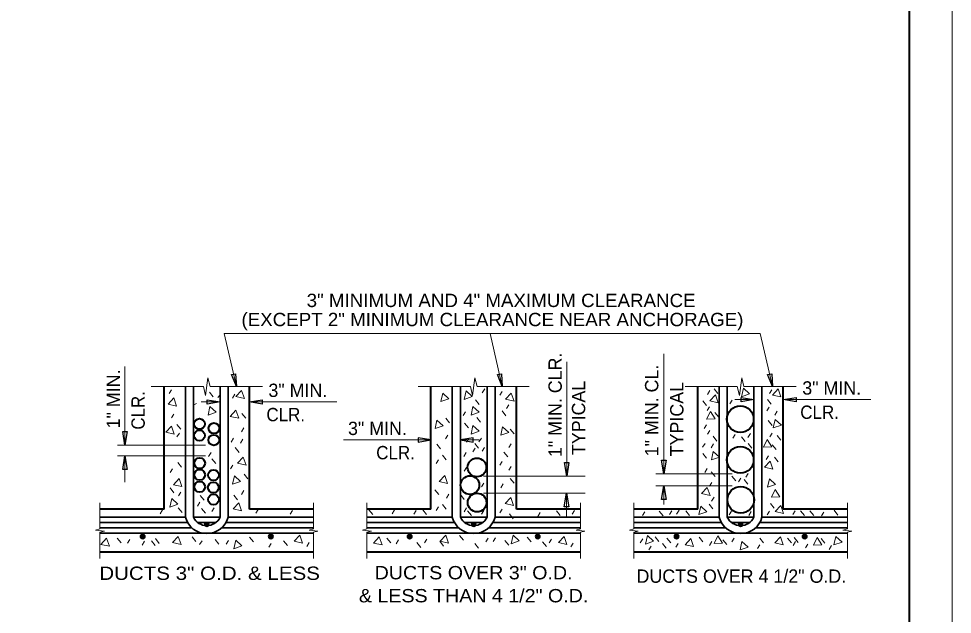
# Model space of a CAD drawing. Extents: x 0 to 22.7, y 0 to 15.6.
# Drawn here: x 15.38 to 22.67, y 4.57 to 9.22 of the extents above; entities that cross this region are included whole.
import ezdxf
from ezdxf.enums import TextEntityAlignment as Align

# ---------------------------------------------------------------- set-up
doc = ezdxf.new("R2010")
doc.units = 0
doc.header["$LTSCALE"] = 0.042
doc.linetypes.add('SHORT_DASHED', pattern=[2.7, 1.5, -1.2])
for name, color, linetype, lineweight in [('1', 7, 'Continuous', 13), ('2', 7, 'SHORT_DASHED', 25), ('3', 7, 'Continuous', 35), ('4', 7, 'Continuous', 13), ('7', 7, 'Continuous', 13)]:
    doc.layers.add(name, color=color, linetype=linetype, lineweight=lineweight)

msp = doc.modelspace()

# ---------------------------------------------------------------- linework, layer by layer
at = {"layer": '1'}
for p, q in [((21.16781, 6.76354), (16.98427, 6.76354)), ((16.82161, 6.34802), (16.41365, 6.34802)), ((17.28167, 6.34802), (16.8737, 6.34802)), ((18.90495, 6.34802), (18.49698, 6.34802)), ((19.365, 6.34802), (18.95703, 6.34802)), ((20.98828, 6.34802), (20.58031, 6.34802)), ((21.44839, 6.34802), (21.04036, 6.34802)), ((21.34964, 6.24552), (21.34766, 6.24552)), ((16.01432, 5.23604), (16.01432, 5.44005)), ((17.68099, 5.23604), (17.68099, 5.44005)), ((18.09766, 5.23604), (18.09766, 5.44005)), ((19.76432, 5.23604), (19.76432, 5.44005)), ((20.18099, 5.23604), (20.18099, 5.44005)), ((21.84766, 5.23604), (21.84766, 5.44005)), ((16.01432, 5.00604), (16.01432, 5.21)), ((17.68099, 5.00604), (17.68099, 5.21)), ((18.09766, 5.00604), (18.09766, 5.21)), ((19.76432, 5.00604), (19.76432, 5.21)), ((20.18099, 5.00604), (20.18099, 5.21)), ((21.84766, 5.00604), (21.84766, 5.21))]:
    msp.add_line(p, q, dxfattribs=at)
at = {"layer": '1', "lineweight": 40}
for p, q in [((16.51432, 5.38969), (16.51432, 6.34802)), ((17.18099, 5.38969), (17.18099, 6.34802)), ((18.59766, 5.38969), (18.59766, 6.34802)), ((19.26432, 5.38969), (19.26432, 6.34802)), ((20.68099, 5.38969), (20.68099, 6.34802)), ((21.34766, 5.38969), (21.34766, 6.34802)), ((16.51432, 5.38969), (16.01432, 5.38969)), ((17.68099, 5.38969), (17.18099, 5.38969)), ((18.59766, 5.38969), (18.09766, 5.38969)), ((19.76432, 5.38969), (19.26432, 5.38969)), ((20.68099, 5.38969), (20.18099, 5.38969)), ((21.84766, 5.38969), (21.34766, 5.38969)), ((16.01432, 5.05635), (17.68099, 5.05635)), ((18.09766, 5.05635), (19.76432, 5.05635)), ((20.18099, 5.05635), (21.84766, 5.05635))]:
    msp.add_line(p, q, dxfattribs=at)
at = {"layer": '1'}
msp.add_lwpolyline([(0, 0), (22.66667, 0), (22.66667, 14.66667), (0, 14.66667)], close=True, dxfattribs=at)
at = {"layer": '1', "lineweight": 40}
msp.add_lwpolyline([(22.33333, 0.33333), (22.33333, 14.33333), (1, 14.33333), (1, 0.33333)], close=True, dxfattribs=at)
at = {"layer": '1'}
for points in [[(16.82161, 6.34802), (16.83896, 6.27859), (16.85635, 6.4175), (16.8737, 6.34802)], [(18.90495, 6.34802), (18.92229, 6.27859), (18.93969, 6.4175), (18.95703, 6.34802)], [(20.98828, 6.34802), (21.00568, 6.27859), (21.02302, 6.4175), (21.04036, 6.34802)], [(16.01432, 5.23604), (15.97958, 5.2274), (16.04906, 5.2187), (16.01432, 5.21)], [(17.68099, 5.23604), (17.64625, 5.2274), (17.71573, 5.2187), (17.68099, 5.21)], [(18.09766, 5.23604), (18.06292, 5.2274), (18.1324, 5.2187), (18.09766, 5.21)], [(19.76432, 5.23604), (19.72958, 5.2274), (19.79906, 5.2187), (19.76432, 5.21)], [(20.18099, 5.23604), (20.1463, 5.2274), (20.21573, 5.2187), (20.18099, 5.21)], [(21.84766, 5.23604), (21.81297, 5.2274), (21.8824, 5.2187), (21.84766, 5.21)]]:
    msp.add_lwpolyline(points, dxfattribs=at)
at = {"layer": '1', "lineweight": 40}
for centre, radius in [((21.01194, 6.09394), 0.10417), ((16.79099, 6.05634), 0.04167), ((16.90411, 6.0228), 0.04167), ((16.79099, 5.96623), 0.04167), ((16.90234, 5.93087), 0.04167), ((21.01194, 5.77545), 0.10417), ((16.79276, 5.75066), 0.04167), ((18.95649, 5.71696), 0.07292), ((16.79276, 5.65878), 0.04167), ((16.90057, 5.65701), 0.04167), ((18.90201, 5.57905), 0.07292), ((16.79276, 5.56514), 0.04167), ((16.8988, 5.55983), 0.04167), ((21.01543, 5.46389), 0.10417), ((16.90057, 5.46618), 0.04167), ((18.95774, 5.44243), 0.07292)]:
    msp.add_circle(centre, radius, dxfattribs=at)
at = {"layer": '2', "linetype": 'Continuous', "lineweight": 35}
for centre, radius in [((16.8474, 5.27233), 0.00173), ((16.8475, 5.27248), 0.000295), ((18.93071, 5.27233), 0.00173), ((18.93082, 5.27248), 0.000295), ((21.01408, 5.27233), 0.00173), ((21.01418, 5.27248), 0.000295)]:
    msp.add_circle(centre, radius, dxfattribs=at)
at = {"layer": '3'}
for p, q in [((16.68099, 5.32719), (16.68099, 6.34802)), ((16.74349, 5.32719), (16.74349, 6.34802)), ((16.95182, 5.32719), (16.95182, 6.34802)), ((17.01432, 5.32719), (17.01432, 6.34802)), ((18.76432, 5.32719), (18.76432, 6.34802)), ((18.82682, 5.32719), (18.82682, 6.34802)), ((19.03516, 5.32719), (19.03516, 6.34802)), ((19.09766, 5.32719), (19.09766, 6.34802)), ((20.84766, 5.32719), (20.84766, 6.34802)), ((20.91016, 5.32719), (20.91016, 6.34802)), ((21.11849, 5.32719), (21.11849, 6.34802)), ((21.18099, 5.32719), (21.18099, 6.34802)), ((16.01432, 5.32719), (16.68099, 5.32719)), ((16.74349, 5.32719), (16.95182, 5.32719)), ((17.01432, 5.32719), (17.68099, 5.32719)), ((18.09766, 5.32719), (18.76432, 5.32719)), ((18.82682, 5.32719), (19.03516, 5.32719)), ((19.09766, 5.32719), (19.76432, 5.32719)), ((20.18099, 5.32719), (20.84766, 5.32719)), ((20.91016, 5.32719), (21.11849, 5.32719)), ((21.18099, 5.32719), (21.84766, 5.32719)), ((16.01432, 5.28552), (16.69885, 5.28552)), ((16.77833, 5.28552), (16.9175, 5.28552)), ((16.99729, 5.28552), (17.68099, 5.28552)), ((18.09766, 5.28552), (18.78219, 5.28552)), ((18.86167, 5.28552), (19.00083, 5.28552)), ((19.08063, 5.28552), (19.76432, 5.28552)), ((20.18099, 5.28552), (20.86557, 5.28552)), ((20.94505, 5.28552), (21.08422, 5.28552)), ((21.16401, 5.28552), (21.84766, 5.28552)), ((16.01432, 5.24385), (16.7324, 5.24385)), ((16.01432, 5.20219), (17.68099, 5.20219)), ((16.96297, 5.24385), (17.68099, 5.24385)), ((18.09766, 5.24385), (18.81573, 5.24385)), ((18.09766, 5.20219), (19.76432, 5.20219)), ((19.0463, 5.24385), (19.76432, 5.24385)), ((20.18099, 5.24385), (20.89911, 5.24385)), ((20.18099, 5.20219), (21.84766, 5.20219)), ((21.12964, 5.24385), (21.84766, 5.24385))]:
    msp.add_line(p, q, dxfattribs=at)
for centre, radius in [((16.84764, 5.27225), 0.01565), ((16.84739, 5.27234), 0.01486), ((16.84739, 5.27234), 0.01486), ((16.84739, 5.27234), 0.01486), ((16.84715, 5.27243), 0.01412), ((16.84715, 5.27243), 0.01412), ((16.84715, 5.27243), 0.01412), ((16.84692, 5.27251), 0.01341), ((16.84764, 5.27225), 0.01043), ((16.84739, 5.27234), 0.00991), ((16.84739, 5.27234), 0.00991), ((16.84739, 5.27234), 0.00991), ((16.84715, 5.27243), 0.00941), ((16.84715, 5.27243), 0.00941), ((16.84715, 5.27243), 0.00941), ((16.84692, 5.27251), 0.00894), ((16.84764, 5.27225), 0.00522), ((16.84739, 5.27234), 0.00496), ((16.84739, 5.27234), 0.00496), ((16.84739, 5.27234), 0.00496), ((16.84715, 5.27243), 0.00471), ((16.84715, 5.27243), 0.00471), ((16.84715, 5.27243), 0.00471), ((16.84692, 5.27251), 0.00447), ((18.93096, 5.27225), 0.01565), ((18.93071, 5.27234), 0.01486), ((18.93071, 5.27234), 0.01486), ((18.93071, 5.27234), 0.01486), ((18.93047, 5.27243), 0.01412), ((18.93047, 5.27243), 0.01412), ((18.93047, 5.27243), 0.01412), ((18.93024, 5.27251), 0.01341), ((18.93096, 5.27225), 0.01043), ((18.93071, 5.27234), 0.00991), ((18.93071, 5.27234), 0.00991), ((18.93071, 5.27234), 0.00991), ((18.93047, 5.27243), 0.00941), ((18.93047, 5.27243), 0.00941), ((18.93047, 5.27243), 0.00941), ((18.93024, 5.27251), 0.00894), ((18.93096, 5.27225), 0.00522), ((18.93071, 5.27234), 0.00496), ((18.93071, 5.27234), 0.00496), ((18.93071, 5.27234), 0.00496), ((18.93047, 5.27243), 0.00471), ((18.93047, 5.27243), 0.00471), ((18.93047, 5.27243), 0.00471), ((18.93024, 5.27251), 0.00447), ((21.01433, 5.27225), 0.01565), ((21.01408, 5.27234), 0.01486), ((21.01408, 5.27234), 0.01486), ((21.01408, 5.27234), 0.01486), ((21.01384, 5.27243), 0.01412), ((21.01384, 5.27243), 0.01412), ((21.01384, 5.27243), 0.01412), ((21.01361, 5.27251), 0.01341), ((21.01433, 5.27225), 0.01043), ((21.01408, 5.27234), 0.00991), ((21.01408, 5.27234), 0.00991), ((21.01408, 5.27234), 0.00991), ((21.01384, 5.27243), 0.00941), ((21.01384, 5.27243), 0.00941), ((21.01384, 5.27243), 0.00941), ((21.01361, 5.27251), 0.00894), ((21.01433, 5.27225), 0.00522), ((21.01408, 5.27234), 0.00496), ((21.01408, 5.27234), 0.00496), ((21.01408, 5.27234), 0.00496), ((21.01384, 5.27243), 0.00471), ((21.01384, 5.27243), 0.00471), ((21.01384, 5.27243), 0.00471), ((21.01361, 5.27251), 0.00447), ((16.34767, 5.1777), 0.01734), ((16.34767, 5.1777), 0.01156), ((16.34767, 5.1777), 0.00578), ((17.34767, 5.1777), 0.01734), ((17.34767, 5.1777), 0.01156), ((17.34767, 5.1777), 0.00578), ((18.43099, 5.1777), 0.01734), ((18.43099, 5.1777), 0.01156), ((18.43099, 5.1777), 0.00578), ((19.43099, 5.1777), 0.01734), ((19.43099, 5.1777), 0.01156), ((19.43099, 5.1777), 0.00578), ((20.51436, 5.1777), 0.01734), ((20.51436, 5.1777), 0.01156), ((20.51436, 5.1777), 0.00578), ((21.51436, 5.1777), 0.01734), ((21.51436, 5.1777), 0.01156), ((21.51436, 5.1777), 0.00578)]:
    msp.add_circle(centre, radius, dxfattribs=at)
for centre, radius, start, end in [((16.84766, 5.37303), 0.17285, 195.36833, 344.63167), ((16.84766, 5.37884), 0.11625, 206.3608, 333.6392), ((18.93097, 5.37303), 0.17285, 195.36833, 344.63167), ((18.93097, 5.37884), 0.11625, 206.3608, 333.6392), ((21.01434, 5.37303), 0.17285, 195.36833, 344.63167), ((21.01434, 5.37884), 0.11625, 206.3608, 333.6392)]:
    msp.add_arc(centre, radius, start, end, dxfattribs=at)
at = {"layer": '4'}
for p, q in [((16.98427, 6.76354), (17.07922, 6.34802)), ((19.05922, 6.76354), (19.15417, 6.34802)), ((21.16781, 6.76354), (21.26276, 6.34802)), ((20.41568, 6.60521), (20.41568, 5.66719)), ((16.20917, 6.5051), (16.20917, 5.88969)), ((19.65672, 6.54109), (19.65672, 5.64927)), ((16.95182, 6.22865), (16.80375, 6.22865)), ((17.86396, 6.22865), (17.18099, 6.22865)), ((21.11849, 6.24714), (20.97047, 6.24714)), ((22.03063, 6.24714), (21.34766, 6.24714)), ((17.91469, 5.93135), (18.59766, 5.93135)), ((18.82682, 5.93135), (18.9749, 5.93135)), ((16.83734, 5.88969), (16.15063, 5.88969)), ((16.83734, 5.80635), (16.15063, 5.80635)), ((16.20917, 5.80635), (16.20917, 5.60104)), ((19.80047, 5.64927), (19.00677, 5.64927)), ((20.94714, 5.66719), (20.35297, 5.66719)), ((20.94714, 5.57271), (20.35297, 5.57271)), ((20.41568, 5.57271), (20.41568, 5.42667)), ((19.80109, 5.51656), (19.00677, 5.51656)), ((19.65542, 5.51667), (19.65542, 5.33135))]:
    msp.add_line(p, q, dxfattribs=at)
at = {"layer": '4', "lineweight": 25}
for points in [[(17.04068, 6.44177), (17.07318, 6.44922), (17.07922, 6.34802)], [(19.11563, 6.44177), (19.14813, 6.44922), (19.15417, 6.34802)], [(21.22422, 6.44177), (21.25672, 6.44922), (21.26276, 6.34802)], [(16.85182, 6.21198), (16.85182, 6.24531), (16.95182, 6.22865)], [(17.28099, 6.24531), (17.28099, 6.21198), (17.18099, 6.22865)], [(21.01849, 6.23047), (21.01849, 6.2638), (21.11849, 6.24714)], [(21.44766, 6.2638), (21.44766, 6.23047), (21.34766, 6.24714)], [(16.19141, 5.99635), (16.22698, 5.99635), (16.20917, 5.88969)], [(18.49766, 5.94802), (18.49766, 5.91469), (18.59766, 5.93135)], [(18.92682, 5.91469), (18.92682, 5.94802), (18.82682, 5.93135)], [(16.22698, 5.69969), (16.19141, 5.69969), (16.20917, 5.80635)], [(20.39786, 5.77385), (20.43344, 5.77385), (20.41568, 5.66719)], [(19.63896, 5.75594), (19.67448, 5.75594), (19.65672, 5.64927)], [(20.43344, 5.46604), (20.39786, 5.46604), (20.41568, 5.57271)], [(19.67318, 5.41), (19.6376, 5.41), (19.65542, 5.51667)]]:
    msp.add_lwpolyline(points, close=True, dxfattribs=at)
at = {"layer": '7'}
for p, q in [((16.57281, 6.32302), (16.55422, 6.29344)), ((16.86781, 6.30479), (16.89734, 6.26792)), ((16.93344, 6.26302), (16.95182, 6.28521)), ((17.06698, 6.28854), (17.04839, 6.25896)), ((19.01703, 6.33), (18.99844, 6.30052)), ((19.15333, 6.31115), (19.13474, 6.28156)), ((20.77516, 6.31677), (20.75661, 6.28719)), ((20.80661, 6.33083), (20.83609, 6.29396)), ((21.25828, 6.32375), (21.23964, 6.29427)), ((16.74521, 6.20406), (16.7674, 6.2151)), ((18.94484, 6.24427), (18.97438, 6.2074)), ((19.20542, 6.20646), (19.18682, 6.17688)), ((20.71911, 6.23625), (20.74859, 6.19938)), ((20.94922, 6.24292), (20.93057, 6.21333)), ((21.22318, 6.24677), (21.25266, 6.2099)), ((16.59031, 6.13396), (16.57172, 6.10438)), ((17.12229, 6.1375), (17.15182, 6.10062)), ((18.86651, 6.15146), (18.84792, 6.12198)), ((19.15214, 6.15802), (19.18167, 6.12115)), ((20.77172, 6.19073), (20.75307, 6.16125)), ((20.81359, 6.14531), (20.84318, 6.10844)), ((21.23724, 6.18729), (21.2187, 6.15771)), ((21.30026, 6.15573), (21.28161, 6.12625)), ((16.61474, 6.05344), (16.64427, 6.01656)), ((18.71245, 6.1024), (18.74198, 6.06552)), ((18.85995, 6.06385), (18.88948, 6.02698)), ((18.95547, 6.10635), (18.985, 6.06948)), ((20.74859, 6.04958), (20.73005, 6.0201)), ((21.23016, 6.08229), (21.25964, 6.04542)), ((16.6338, 5.98479), (16.61521, 5.95531)), ((17.13635, 6.02552), (17.11776, 5.99594)), ((19.21651, 6.0149), (19.24604, 5.97802)), ((20.77516, 6.00521), (20.75661, 5.97573)), ((21.09026, 5.98073), (21.07161, 5.95125)), ((21.26172, 5.98427), (21.24318, 5.95469)), ((17.05589, 5.945), (17.03729, 5.91542)), ((17.12901, 5.93688), (17.11042, 5.90729)), ((18.73, 5.96948), (18.71141, 5.9399)), ((18.89302, 5.94365), (18.87443, 5.91406)), ((18.93953, 5.90479), (18.96906, 5.86792)), ((18.99073, 5.94667), (18.97214, 5.91719)), ((20.73672, 5.90375), (20.71807, 5.87417)), ((20.79964, 5.95979), (20.82911, 5.92292)), ((20.9712, 5.97375), (20.95266, 5.94417)), ((21.02005, 5.95625), (21.04964, 5.91938)), ((21.07255, 5.90375), (21.10214, 5.86688)), ((21.29839, 5.96563), (21.32786, 5.92875)), ((16.88083, 5.83292), (16.86224, 5.80344)), ((17.06979, 5.87146), (17.09932, 5.83458)), ((18.64245, 5.89948), (18.67198, 5.8626)), ((18.87349, 5.83292), (18.8549, 5.80344)), ((18.94297, 5.86719), (18.92438, 5.8376)), ((19.01479, 5.87385), (18.9962, 5.84427)), ((19.1675, 5.83646), (19.19703, 5.79958)), ((19.22344, 5.90156), (19.20484, 5.87198)), ((20.80318, 5.90021), (20.78464, 5.87073)), ((21.26161, 5.89323), (21.2912, 5.85635)), ((16.88776, 5.78396), (16.91729, 5.74708)), ((18.65651, 5.77698), (18.63792, 5.7474)), ((18.68792, 5.81188), (18.71745, 5.775)), ((19.15406, 5.76333), (19.13547, 5.73385)), ((20.71911, 5.82677), (20.74859, 5.7899)), ((21.23276, 5.8075), (21.21411, 5.77802)), ((21.27776, 5.79688), (21.30724, 5.76)), ((16.57984, 5.70698), (16.56125, 5.6774)), ((16.62115, 5.75646), (16.65068, 5.71958)), ((17.05234, 5.7349), (17.03375, 5.70542)), ((18.87422, 5.71594), (18.85562, 5.68646)), ((19.22354, 5.72448), (19.20495, 5.6949)), ((20.75422, 5.70771), (20.73557, 5.67823)), ((17.13979, 5.6649), (17.16932, 5.62802)), ((19.21651, 5.6299), (19.24604, 5.59302)), ((20.78557, 5.68323), (20.81516, 5.64635)), ((20.94661, 5.64823), (20.97609, 5.61135)), ((21.01672, 5.63417), (20.99818, 5.60469)), ((21.04109, 5.62365), (21.07068, 5.58677)), ((21.07276, 5.66917), (21.05411, 5.63969)), ((16.56224, 5.55646), (16.59177, 5.51958)), ((18.62844, 5.5424), (18.65797, 5.50552)), ((19.01083, 5.59365), (18.99224, 5.56406)), ((19.16057, 5.58792), (19.14198, 5.55844)), ((20.78922, 5.59917), (20.77057, 5.56969)), ((16.6463, 5.5249), (16.62771, 5.49542)), ((16.79677, 5.49688), (16.8263, 5.46)), ((17.05927, 5.50042), (17.0888, 5.46354)), ((17.13635, 5.53542), (17.11776, 5.50594)), ((18.73703, 5.5074), (18.71844, 5.47792)), ((18.82745, 5.50448), (18.85698, 5.4676)), ((20.80672, 5.48365), (20.78807, 5.45417)), ((16.62526, 5.4024), (16.65479, 5.36552)), ((16.79333, 5.44437), (16.77474, 5.4149)), ((16.80724, 5.39542), (16.83677, 5.35854)), ((16.90536, 5.4024), (16.88677, 5.37292)), ((18.65651, 5.40938), (18.63792, 5.3799)), ((18.68792, 5.42688), (18.71745, 5.39)), ((18.87557, 5.40031), (18.85698, 5.37083)), ((20.76807, 5.43125), (20.79766, 5.39438)), ((21.24766, 5.43469), (21.27714, 5.39781)), ((16.50281, 5.3849), (16.48422, 5.35542)), ((17.24839, 5.38844), (17.22979, 5.35885)), ((17.51792, 5.38146), (17.49932, 5.35188)), ((18.11391, 5.3849), (18.14344, 5.34802)), ((18.31349, 5.3849), (18.2949, 5.35542)), ((18.48151, 5.38146), (18.46292, 5.35188)), ((18.53391, 5.3849), (18.56344, 5.34802)), ((18.88349, 5.3774), (18.91302, 5.34052)), ((19.01, 5.38146), (18.99141, 5.35188)), ((19.15354, 5.39188), (19.13495, 5.3624)), ((19.20948, 5.35333), (19.23901, 5.31646)), ((19.45109, 5.36396), (19.4325, 5.33438)), ((19.57703, 5.37792), (19.60656, 5.34104)), ((19.71708, 5.38146), (19.69849, 5.35188)), ((20.26766, 5.3713), (20.24911, 5.34177)), ((20.37953, 5.37448), (20.40911, 5.3376)), ((20.47766, 5.37865), (20.45911, 5.34917)), ((20.5337, 5.38219), (20.51505, 5.3526)), ((20.58609, 5.37875), (20.61557, 5.34187)), ((20.94318, 5.37521), (20.92464, 5.34563)), ((21.09724, 5.37167), (21.07859, 5.34219)), ((21.24078, 5.37521), (21.22214, 5.34563)), ((21.44026, 5.37865), (21.42172, 5.34917)), ((21.48214, 5.37875), (21.51172, 5.34187)), ((21.55568, 5.37875), (21.58516, 5.34187)), ((21.66432, 5.36823), (21.64568, 5.33865)), ((21.74464, 5.38219), (21.77422, 5.34531)), ((16.73375, 5.1749), (16.76328, 5.13802)), ((18.82094, 5.18542), (18.85047, 5.14854)), ((20.34719, 5.17573), (20.37672, 5.13885)), ((16.14922, 5.16438), (16.17875, 5.1275)), ((16.24729, 5.15385), (16.2287, 5.12438)), ((16.36281, 5.1399), (16.34422, 5.11031)), ((16.41521, 5.14333), (16.44474, 5.10646)), ((16.44672, 5.16083), (16.47625, 5.12396)), ((16.81083, 5.14344), (16.79224, 5.11385)), ((16.91229, 5.15385), (16.94182, 5.11698)), ((17.01734, 5.14688), (16.99875, 5.1174)), ((17.18177, 5.17135), (17.2113, 5.13448)), ((17.3499, 5.1224), (17.3313, 5.09281)), ((17.44781, 5.14333), (17.47734, 5.10646)), ((17.6474, 5.12938), (17.6288, 5.0999)), ((18.25391, 5.16438), (18.28344, 5.1275)), ((18.345, 5.15042), (18.32641, 5.12083)), ((18.48844, 5.12938), (18.51797, 5.0925)), ((18.56552, 5.1574), (18.54693, 5.12781)), ((18.66693, 5.1399), (18.69646, 5.10302)), ((18.93995, 5.1224), (18.96948, 5.08552)), ((19.04505, 5.16438), (19.02646, 5.1349)), ((19.10104, 5.16792), (19.08245, 5.13833)), ((19.17448, 5.14688), (19.20401, 5.11)), ((19.34948, 5.17135), (19.37901, 5.13448)), ((19.46849, 5.13635), (19.49802, 5.09948)), ((19.53859, 5.1574), (19.52, 5.12781)), ((19.70661, 5.12594), (19.68802, 5.09635)), ((20.25016, 5.15813), (20.23161, 5.12865)), ((20.31594, 5.10313), (20.29734, 5.07359)), ((20.40401, 5.1225), (20.43359, 5.08563)), ((20.43911, 5.16521), (20.46859, 5.12833)), ((20.52672, 5.12312), (20.50807, 5.09365)), ((20.69109, 5.17219), (20.72057, 5.13531)), ((20.78922, 5.13719), (20.77057, 5.1076)), ((20.87661, 5.15115), (20.90609, 5.11427)), ((20.96422, 5.16521), (20.94568, 5.13563)), ((21.1637, 5.11271), (21.14516, 5.08312)), ((21.16359, 5.16521), (21.19318, 5.12833)), ((21.38068, 5.16521), (21.41016, 5.12833)), ((21.4438, 5.13719), (21.42516, 5.1076)), ((21.43318, 5.16865), (21.46266, 5.13177)), ((21.54016, 5.11823), (21.52156, 5.08875)), ((21.64318, 5.16167), (21.67266, 5.12479)), ((21.72443, 5.10609), (21.70583, 5.07656))]:
    msp.add_line(p, q, dxfattribs=at)
for points in [[(17.07453, 6.27094), (17.11891, 6.31896), (17.14094, 6.25615)], [(18.68948, 6.29708), (18.73745, 6.25281), (18.67474, 6.23073)], [(18.87188, 6.31417), (18.91984, 6.27), (18.85714, 6.24792)], [(19.17938, 6.2499), (19.22375, 6.29792), (19.24573, 6.23521)], [(20.77286, 6.23667), (20.81724, 6.28469), (20.83922, 6.22198)], [(21.0363, 6.33568), (21.08432, 6.29146), (21.02161, 6.26938)], [(21.26286, 6.28219), (21.30724, 6.33021), (21.32932, 6.2675)], [(16.54594, 6.21135), (16.59031, 6.25938), (16.61234, 6.19667)], [(16.87281, 6.19193), (16.92078, 6.14771), (16.85807, 6.12563)], [(17.03036, 6.11521), (17.07474, 6.16323), (17.09677, 6.10052)], [(18.92505, 6.19229), (18.97302, 6.14813), (18.91031, 6.12604)], [(20.81464, 6.09583), (20.74932, 6.09323), (20.77807, 6.15323)], [(18.64391, 6.08625), (18.69187, 6.04198), (18.62917, 6.0199)], [(21.28411, 6.0924), (21.33214, 6.04813), (21.26943, 6.02604)], [(16.52703, 5.99156), (16.57141, 6.03958), (16.59344, 5.97688)], [(18.92505, 6.04375), (18.97302, 5.99958), (18.91031, 5.9775)], [(19.15677, 6.0349), (19.20474, 5.99063), (19.14203, 5.96854)], [(21.25911, 5.87875), (21.19391, 5.87615), (21.22266, 5.93625)], [(20.80109, 5.84198), (20.84901, 5.79781), (20.7863, 5.77573)], [(17.08854, 5.74938), (17.13292, 5.7974), (17.15495, 5.73458)], [(21.19984, 5.71865), (21.24422, 5.76667), (21.2663, 5.70396)], [(16.58797, 5.58135), (16.63234, 5.62938), (16.65438, 5.56667)], [(17.06427, 5.65219), (17.11224, 5.60792), (17.04953, 5.58583)], [(18.66115, 5.60583), (18.70552, 5.65385), (18.72755, 5.59115)], [(21.23865, 5.62849), (21.28661, 5.58427), (21.22391, 5.56219)], [(20.70984, 5.51219), (20.75422, 5.56021), (20.7762, 5.4974)], [(21.32078, 5.48677), (21.25552, 5.48417), (21.28427, 5.54417)], [(16.57422, 5.47365), (16.62219, 5.42948), (16.55948, 5.4074)], [(19.17573, 5.43438), (19.2201, 5.4824), (19.24214, 5.41958)], [(17.05354, 5.39229), (17.09792, 5.44031), (17.11995, 5.3776)], [(20.70307, 5.4149), (20.75099, 5.37073), (20.68828, 5.34865)], [(21.28391, 5.37219), (21.32828, 5.42021), (21.35026, 5.3574)], [(16.58099, 5.12979), (16.62536, 5.17781), (16.6474, 5.1151)], [(17.52958, 5.14031), (17.57396, 5.18833), (17.59599, 5.12563)], [(18.1501, 5.12635), (18.19448, 5.17438), (18.21651, 5.11156)], [(18.66818, 5.14031), (18.71255, 5.18833), (18.73458, 5.12563)], [(19.23896, 5.18667), (19.28693, 5.1424), (19.22422, 5.12031)], [(19.59224, 5.12979), (19.63661, 5.17781), (19.65865, 5.1151)], [(20.28771, 5.18453), (20.33568, 5.14031), (20.27297, 5.11823)], [(20.87411, 5.12625), (20.80891, 5.12365), (20.83766, 5.18365)], [(21.28036, 5.12708), (21.32474, 5.1751), (21.34682, 5.1124)], [(21.75771, 5.17771), (21.80568, 5.13354), (21.74297, 5.11146)], [(16.02094, 5.11583), (16.06531, 5.16385), (16.08734, 5.10104)], [(17.07474, 5.14813), (17.12271, 5.10385), (17.06, 5.08177)], [(20.58036, 5.11313), (20.62474, 5.16115), (20.64672, 5.09833)], [(21.02505, 5.13844), (21.07307, 5.09417), (21.01036, 5.07208)], [(21.64766, 5.11219), (21.58245, 5.10958), (21.6112, 5.16969)]]:
    msp.add_lwpolyline(points, close=True, dxfattribs=at)

# ---------------------------------------------------------------- texts
at = {"layer": '4'}
for s, height, width, p in [('3" MINIMUM AND 4" MAXIMUM CLEARANCE', 0.1041, 1.05, (19.14516, 6.96943)), ('(EXCEPT 2" MINIMUM CLEARANCE NEAR ANCHORAGE)', 0.1041, 1.05, (19.0774, 6.82026)), ('DUCTS 3" O.D. & LESS', 0.1042, 1.15, (16.86984, 4.83828)), ('DUCTS OVER 3" O.D.', 0.1042, 1.1, (18.93031, 4.84271)), ('& LESS THAN 4 1/2" O.D.', 0.1041, 1.1, (18.93029, 4.66312))]:
    msp.add_text(s, height=height, dxfattribs=dict(at, width=width)).set_placement(p, align=Align.CENTER)
for s, p in [('1" MIN. CLR.', (19.6187, 5.79818)), ('1" MIN. CL.', (20.37214, 5.80396)), ('1" MIN.', (16.1701, 6.02229)), ('TYPICAL', (19.80135, 5.81328)), ('TYPICAL', (20.56839, 5.80375))]:
    msp.add_text(s, height=0.1042, rotation=90, dxfattribs=at).set_placement(p)
for p in [(17.32896, 6.26724), (21.49563, 6.28573), (17.95036, 5.96995)]:
    msp.add_text('3" MIN.', height=0.1041, dxfattribs=at).set_placement(p)
at = {"layer": '4', "width": 0.95}
msp.add_text('CLR.', height=0.1041, rotation=90, dxfattribs=at).set_placement((16.3638, 6.01177))
for p in [(21.47979, 6.09604), (17.31312, 6.07755), (18.17031, 5.78026)]:
    msp.add_text('CLR.', height=0.1042, dxfattribs=at).set_placement(p)
at = {"layer": '4'}
msp.add_text('DUCTS OVER 4 1/2" O.D.', height=0.1042, dxfattribs=at).set_placement((21.02008, 4.81578), align=Align.CENTER)

doc.saveas('drawing.dxf')
